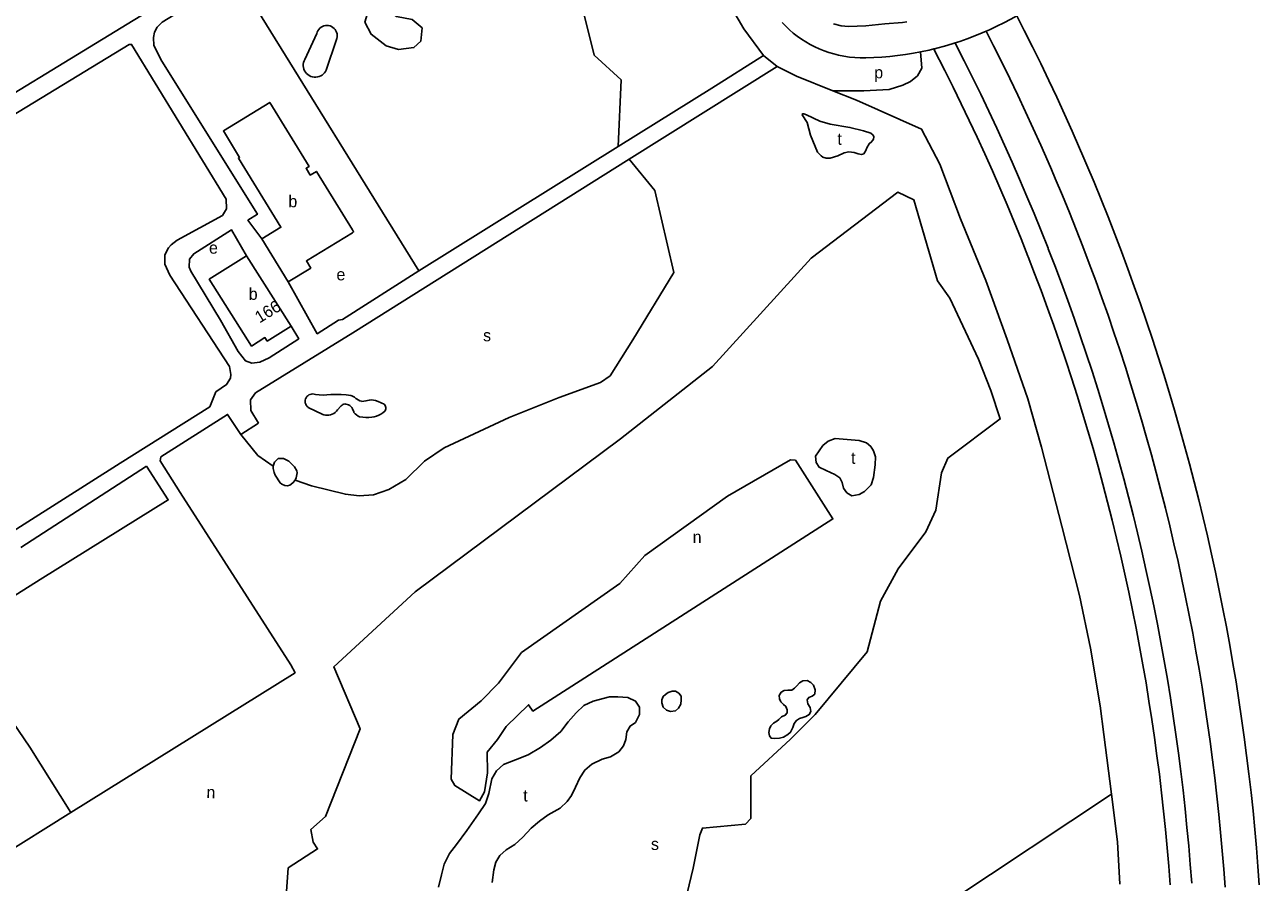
# Model space of a CAD drawing. Extents: x 156066 to 157805, y 383432 to 385631.
# Drawn here: x 157390.3 to 157803.6, y 384159.6 to 384446.9 of the extents above; entities that cross this region are included whole.
import ezdxf

# ---------------------------------------------------------------- set-up
doc = ezdxf.new("R2010")
doc.units = 0
for name, color, linetype in [('BLT_Basislijn', 7, 'Continuous'), ('BLT_Bebouwing', 7, 'Continuous'), ('BLT_Centroide', 7, 'Continuous'), ('BLT_Huisnummer', 7, 'Continuous'), ('BLT_Vlakafsluiter', 7, 'Continuous')]:
    doc.layers.add(name, color=color, linetype=linetype)

msp = doc.modelspace()

# ---------------------------------------------------------------- linework, layer by layer
at = {"layer": 'BLT_Basislijn'}
for p, q in [((157522.22, 384364.48), (157461.24, 384463.14)), ((157484.02, 384435.3), (157488.07, 384443.93)), ((157494.66, 384441.97), (157491.2, 384431.64)), ((157637.62, 384436.63), (157642.15, 384432.95)), ((157592.68, 384401.87), (157642.15, 384432.95)), ((157522.22, 384364.48), (157588.98, 384406.1)), ((157500.12, 384343.73), (157592.68, 384401.87)), ((157467.49, 384323.6), (157500.12, 384343.73)), ((157465.84, 384321.27), (157467.49, 384323.6)), ((157494.96, 384317.92), (157496.14, 384319.1)), ((157503.01, 384320.77), (157503.11, 384320.75)), ((157485.22, 384318.7), (157490.12, 384316.34)), ((157462.66, 384309.61), (157468.56, 384313.45)), ((157388.98, 384271.84), (157431.02, 384299.07))]:
    msp.add_line(p, q, dxfattribs=at)
for points in [[(157577.97, 384534.34), (157586.11, 384522.12), (157595.63, 384507.58), (157604.85, 384491.61), (157613.92, 384476.32), (157625.31, 384455.34), (157631.08, 384445.59), (157637.62, 384436.63)], [(157563.05, 384525.09), (157562.14, 384517.39), (157562.53, 384511.91), (157563.85, 384508.09), (157567.99, 384492.58), (157572.95, 384468.76), (157580.92, 384436.73), (157589.99, 384428.45), (157588.98, 384406.1)], [(157511.3, 384500), (157466.93, 384473.08), (157321.03, 384383.89)], [(157461.24, 384463.14), (157436.28, 384447.8), (157434.62, 384446.05), (157433.67, 384444.46), (157433.38, 384442.61), (157433.51, 384439.9), (157436.22, 384434.71), (157468.2, 384383.41), (157464.98, 384381.42), (157469.68, 384375.15)], [(157690.21, 384437.84), (157687.81, 384437.39), (157685.18, 384436.96), (157682.53, 384436.59), (157679.88, 384436.29), (157677.22, 384436.06), (157674.53, 384435.89), (157671.84, 384435.79), (157670.01, 384435.8), (157668.18, 384435.89), (157666.36, 384436.07), (157664.56, 384436.34), (157662.77, 384436.71), (157661.11, 384437.12), (157659.48, 384437.62), (157657.88, 384438.18), (157656.3, 384438.83), (157654.75, 384439.54), (157653.24, 384440.32), (157651.77, 384441.18), (157650.33, 384442.1), (157648.94, 384443.09), (157647.6, 384444.14), (157646.31, 384445.25), (157645.07, 384446.42), (157643.89, 384447.64)], [(157685.58, 384447.87), (157684.2, 384447.69), (157678.27, 384447.2), (157671.88, 384446.56), (157666.07, 384446.28), (157663.66, 384446.56), (157661.04, 384447.2)], [(157722.4, 384449.93), (157720.43, 384448.82), (157718.07, 384447.57), (157715.68, 384446.38), (157713.26, 384445.25), (157712.13, 384444.75)], [(157803.61, 384158.76), (157803.16, 384164.97), (157802.66, 384171.17), (157802.1, 384177.37), (157801.5, 384183.57), (157800.84, 384189.76), (157800.13, 384195.95), (157799.37, 384202.13), (157798.56, 384208.3), (157797.69, 384214.47), (157796.78, 384220.63), (157795.81, 384226.78), (157794.8, 384232.92), (157793.73, 384239.06), (157792.61, 384245.18), (157791.44, 384251.3), (157790.21, 384257.4), (157788.94, 384263.5), (157787.62, 384269.58), (157786.25, 384275.66), (157784.82, 384281.72), (157783.35, 384287.77), (157781.82, 384293.8), (157780.25, 384299.83), (157778.62, 384305.84), (157776.94, 384311.84), (157775.22, 384317.82), (157773.44, 384323.79), (157771.62, 384329.74), (157769.74, 384335.68), (157767.82, 384341.6), (157765.85, 384347.51), (157763.82, 384353.39), (157761.75, 384359.27), (157759.63, 384365.12), (157757.46, 384370.96), (157755.25, 384376.78), (157752.98, 384382.58), (157750.67, 384388.36), (157748.3, 384394.12), (157745.89, 384399.86), (157744.56, 384402.97), (157743.44, 384405.58), (157740.93, 384411.28), (157738.38, 384416.96), (157735.78, 384422.62), (157733.13, 384428.25), (157730.44, 384433.87), (157727.69, 384439.46), (157724.91, 384445.03), (157722.4, 384449.93)], [(157488.07, 384443.93), (157488.22, 384444.43), (157488.44, 384444.91), (157488.73, 384445.34), (157489.09, 384445.73), (157489.5, 384446.06), (157489.95, 384446.32), (157490.44, 384446.51), (157490.95, 384446.62), (157491.48, 384446.66), (157492, 384446.61), (157492.51, 384446.49), (157493, 384446.29), (157493.45, 384446.02), (157493.85, 384445.68), (157494.2, 384445.29), (157494.48, 384444.85), (157494.69, 384444.37), (157494.83, 384443.86), (157494.89, 384443.34), (157494.87, 384442.82), (157494.77, 384442.3), (157494.66, 384441.97)], [(157712.13, 384444.75), (157710.81, 384444.18), (157708.34, 384443.17), (157705.84, 384442.22), (157703.32, 384441.34), (157701.73, 384440.82)], [(157712.13, 384444.75), (157714.65, 384439.83), (157717.39, 384434.35), (157720.09, 384428.85), (157722.74, 384423.32), (157725.35, 384417.77), (157727.91, 384412.2), (157730.42, 384406.61), (157732.89, 384401), (157734, 384398.42), (157735.31, 384395.36), (157737.68, 384389.71), (157740.01, 384384.04), (157742.29, 384378.35), (157744.52, 384372.64), (157746.7, 384366.91), (157748.84, 384361.16), (157750.92, 384355.4), (157752.96, 384349.61), (157754.95, 384343.82), (157756.9, 384338), (157758.79, 384332.17), (157760.64, 384326.32), (157762.43, 384320.46), (157764.18, 384314.59), (157765.88, 384308.69), (157767.53, 384302.79), (157769.13, 384296.87), (157770.68, 384290.94), (157772.19, 384285), (157773.64, 384279.04), (157775.04, 384273.07), (157776.39, 384267.09), (157777.7, 384261.1), (157778.95, 384255.1), (157780.15, 384249.09), (157781.3, 384243.07), (157782.41, 384237.04), (157783.46, 384231), (157784.46, 384224.95), (157785.41, 384218.89), (157786.31, 384212.83), (157787.16, 384206.76), (157787.96, 384200.68), (157788.71, 384194.59), (157789.41, 384188.5), (157790.06, 384182.4), (157790.65, 384176.3), (157791.2, 384170.2), (157791.69, 384164.09), (157792.14, 384157.97)], [(157321.16, 384235.84), (157422.22, 384300), (157452.28, 384318.94), (157454.21, 384323.92), (157457.87, 384326.37), (157459.12, 384328.47), (157459.31, 384329.8), (157458.83, 384332.42), (157438.86, 384363.06), (157437.2, 384366.69), (157437.22, 384369.84), (157438.41, 384372.18), (157439.25, 384373.17), (157441.31, 384374.78), (157456.44, 384383.06), (157457.87, 384385.19), (157457.71, 384388.47), (157426.03, 384440.3), (157425.29, 384440.34), (157257.34, 384338.04)], [(157701.73, 384440.82), (157700.78, 384440.52), (157698.22, 384439.76), (157695.64, 384439.07), (157694.61, 384438.82)], [(157701.73, 384440.82), (157701.75, 384440.78)], [(157701.75, 384440.78), (157704.8, 384434.81), (157707.6, 384429.22), (157710.35, 384423.6), (157713.05, 384417.96), (157715.71, 384412.3), (157718.31, 384406.61), (157720.86, 384400.91), (157723.37, 384395.18), (157725.83, 384389.42), (157728.23, 384383.65), (157730.59, 384377.86), (157732.89, 384372.05), (157732.97, 384371.85), (157735.15, 384366.21), (157737.35, 384360.36), (157739.51, 384354.49), (157741.61, 384348.6), (157743.67, 384342.69), (157745.67, 384336.77), (157747.62, 384330.83), (157749.52, 384324.87), (157751.37, 384318.89), (157753.16, 384312.9), (157754.91, 384306.9), (157756.6, 384300.88), (157758.24, 384294.84), (157759.83, 384288.79), (157761.37, 384282.73), (157762.85, 384276.66), (157764.28, 384270.57), (157765.66, 384264.47), (157766.99, 384258.36), (157768.26, 384252.24), (157769.48, 384246.1), (157770.65, 384239.96), (157771.77, 384233.8), (157772.83, 384227.64), (157773.83, 384221.47), (157774.79, 384215.29), (157775.69, 384209.1), (157776.54, 384202.9), (157777.33, 384196.7), (157778.07, 384190.49), (157778.76, 384184.27), (157779.4, 384178.05), (157779.98, 384171.83), (157780.5, 384165.59), (157780.97, 384159.36)], [(157484.02, 384435.3), (157483.78, 384434.79), (157483.62, 384434.24), (157483.54, 384433.68), (157483.54, 384433.11), (157483.61, 384432.55), (157483.77, 384432), (157484, 384431.48), (157484.3, 384431), (157484.66, 384430.57), (157485.08, 384430.19), (157485.55, 384429.87), (157486.07, 384429.62), (157486.61, 384429.45), (157487.17, 384429.36), (157487.73, 384429.34), (157488.3, 384429.41), (157488.85, 384429.55), (157489.37, 384429.77), (157489.86, 384430.06), (157490.3, 384430.41), (157490.69, 384430.83), (157491.02, 384431.29), (157491.2, 384431.64)], [(157588.98, 384406.1), (157620.35, 384425.66), (157637.62, 384436.63)], [(157690.21, 384437.84), (157690.65, 384432.4), (157689.16, 384429.83), (157686.85, 384427.9), (157684.23, 384426.67), (157679.68, 384425.23), (157671.23, 384424.74), (157660.82, 384424.81)], [(157694.61, 384438.82), (157693.05, 384438.44), (157690.21, 384437.84)], [(157694.61, 384438.82), (157694.63, 384438.78)], [(157694.63, 384438.78), (157698.33, 384431.54), (157701.1, 384426), (157703.83, 384420.44), (157706.5, 384414.86), (157709.13, 384409.25), (157711.7, 384403.62), (157714.23, 384397.97), (157716.71, 384392.3), (157719.15, 384386.61), (157721.53, 384380.89), (157723.86, 384375.16), (157726.14, 384369.4), (157726.22, 384369.21), (157728.38, 384363.63), (157730.56, 384357.83), (157732.69, 384352.02), (157734.78, 384346.19), (157736.81, 384340.34), (157738.79, 384334.48), (157740.72, 384328.6), (157742.6, 384322.7), (157744.43, 384316.78), (157746.21, 384310.85), (157747.94, 384304.91), (157749.61, 384298.95), (157751.24, 384292.97), (157752.81, 384286.98), (157754.33, 384280.98), (157755.8, 384274.97), (157757.22, 384268.94), (157758.58, 384262.9), (157759.9, 384256.85), (157761.16, 384250.79), (157762.37, 384244.72), (157763.52, 384238.63), (157764.63, 384232.54), (157765.68, 384226.44), (157766.67, 384220.33), (157767.62, 384214.21), (157768.51, 384208.09), (157769.35, 384201.95), (157770.14, 384195.81), (157770.87, 384189.66), (157771.55, 384183.51), (157772.18, 384177.35), (157772.75, 384171.18), (157773.27, 384165.02), (157773.74, 384158.84)], [(157642.15, 384432.95), (157648.62, 384429.7), (157660.82, 384424.81)], [(157660.82, 384424.81), (157668.78, 384421.61), (157690.52, 384411.94), (157696.66, 384400.17), (157703.56, 384381.88), (157712.1, 384361.2), (157719.15, 384341.49), (157726.12, 384321.63), (157730.69, 384305.44), (157737.51, 384278.98), (157743.43, 384255.67), (157747.1, 384238.06), (157750.33, 384218.79), (157751.57, 384209.13)], [(157480.78, 384294.34), (157486.24, 384292.43), (157497.65, 384289.61), (157502.2, 384289.1), (157507.06, 384289.47), (157512.13, 384291.22), (157517.82, 384294.54), (157524.17, 384300.75), (157530.71, 384305.15), (157552.45, 384315.33), (157569.18, 384322.09), (157583.06, 384327.05), (157586.27, 384329.35), (157593.9, 384341.35), (157607.59, 384363.86), (157601.18, 384391.37), (157592.68, 384401.87)], [(157477.7, 384153.46), (157478.43, 384164.44), (157488.31, 384170.82), (157486.9, 384173.09), (157486.12, 384177.28), (157490.97, 384181.73), (157502.56, 384211.02), (157493.71, 384231.83), (157521.01, 384256.9), (157589.79, 384308.16), (157620.57, 384332.39), (157653.52, 384368.69), (157682.63, 384390.78), (157687.95, 384388.27), (157695.87, 384361.09), (157700, 384355.32), (157709.58, 384334.85), (157713.77, 384324.42), (157716.89, 384314.86), (157699.29, 384301.76), (157697.26, 384296.78), (157695.36, 384284.33), (157691.95, 384277.05), (157682.71, 384264.6), (157676.77, 384253.86), (157672.33, 384236.85), (157654.86, 384215.86), (157646.62, 384207.6), (157633.37, 384195.29), (157633.35, 384181.06), (157631.6, 384179.13), (157617.18, 384177.79), (157616.3, 384175.54), (157614.03, 384164.34), (157610.59, 384150.01)], [(157479.43, 384345.96), (157482, 384341.72), (157472.11, 384335.35), (157469, 384333.85), (157466.31, 384333.53), (157464.18, 384334.27), (157461.71, 384337.5), (157455.8, 384347.98), (157445.84, 384364.41), (157445.33, 384365.73), (157445.45, 384368.41), (157446.89, 384370.22), (157459.52, 384378.16), (157464.5, 384369.51)], [(157522.22, 384364.48), (157496.66, 384348.18), (157495.29, 384347.99), (157488.19, 384343.41), (157478.51, 384360.75)], [(157487.59, 384323.04), (157487.16, 384323.17), (157486.72, 384323.22), (157486.27, 384323.2), (157485.84, 384323.09), (157485.43, 384322.91), (157485.07, 384322.65), (157484.75, 384322.34), (157484.49, 384321.97), (157484.31, 384321.57), (157484.2, 384321.14), (157484.17, 384320.69), (157484.21, 384320.25), (157484.34, 384319.82), (157484.54, 384319.42), (157484.81, 384319.07), (157485.14, 384318.77), (157485.22, 384318.7)], [(157468.56, 384313.45), (157465.99, 384317.68), (157465.84, 384321.27)], [(157487.59, 384323.04), (157488.87, 384322.92), (157490.17, 384322.87), (157491.46, 384322.9), (157492.75, 384323.01), (157492.99, 384323.04)], [(157492.99, 384323.04), (157494.62, 384323.07), (157496.24, 384323.03), (157497.87, 384322.9), (157499.48, 384322.69), (157499.75, 384322.65)], [(157497.83, 384319.83), (157497.48, 384319.87), (157497.13, 384319.82), (157496.8, 384319.7), (157496.5, 384319.51), (157496.25, 384319.26), (157496.14, 384319.1)], [(157500.03, 384318.25), (157499.79, 384318.66), (157499.48, 384319.03), (157499.12, 384319.33), (157498.71, 384319.57), (157498.26, 384319.74), (157497.83, 384319.83)], [(157499.75, 384322.65), (157500.26, 384322.41), (157500.72, 384322.11), (157501.14, 384321.74), (157501.33, 384321.54)], [(157501.33, 384321.54), (157501.86, 384321.21), (157502.42, 384320.96), (157503.01, 384320.77)], [(157503.11, 384320.75), (157503.8, 384320.79), (157504.48, 384320.9), (157505.04, 384321.07)], [(157507.67, 384321.07), (157507.02, 384321.18), (157506.36, 384321.23), (157505.7, 384321.19), (157505.04, 384321.07)], [(157510.64, 384319.79), (157509.65, 384320.3), (157508.63, 384320.73), (157507.67, 384321.07)], [(157510.93, 384317.54), (157511.09, 384317.89), (157511.17, 384318.27), (157511.17, 384318.65), (157511.09, 384319.03), (157510.94, 384319.38), (157510.72, 384319.7), (157510.64, 384319.79)], [(157435.81, 384302.14), (157458.18, 384316.38), (157462.66, 384309.61)], [(157494.96, 384317.92), (157494.61, 384317.46), (157494.19, 384317.06), (157493.73, 384316.72), (157493.22, 384316.45), (157492.68, 384316.26), (157492.12, 384316.13), (157491.54, 384316.09), (157490.97, 384316.13), (157490.41, 384316.25), (157490.12, 384316.34)], [(157500.03, 384318.25), (157500.44, 384317.22), (157500.5, 384317.07)], [(157500.5, 384317.07), (157500.9, 384316.59), (157501.35, 384316.18), (157501.86, 384315.83), (157502.41, 384315.54)], [(157502.41, 384315.54), (157503.43, 384315.4), (157504.46, 384315.33), (157505.49, 384315.35), (157506.52, 384315.45), (157507.31, 384315.58)], [(157507.31, 384315.58), (157508.08, 384315.81), (157508.83, 384316.11), (157509.54, 384316.49), (157510.2, 384316.93), (157510.83, 384317.44), (157510.93, 384317.54)], [(157462.66, 384309.61), (157468.33, 384302.64), (157473.47, 384299.03)], [(157431.02, 384299.07), (157438.34, 384287.74), (157395.47, 384261.06)], [(157435.81, 384302.14), (157435.58, 384300.77), (157442.36, 384290.25), (157479.39, 384232.46), (157480.77, 384229.86), (157405.66, 384183.03)], [(157473.47, 384299.03), (157473.92, 384300.4), (157475.12, 384301.59), (157476.86, 384301.66), (157478.66, 384300.73), (157480.65, 384298.87), (157481.39, 384297.46), (157481.45, 384296.86), (157481.14, 384295.14), (157480.78, 384294.34)], [(157480.78, 384294.34), (157480.04, 384293.41), (157479.08, 384292.7), (157478.26, 384292.43), (157477.32, 384292.52), (157476.32, 384292.98), (157475.83, 384293.45), (157474.17, 384296.05), (157473.83, 384296.9), (157473.49, 384298.28), (157473.47, 384299.03)], [(157372.75, 384226.84), (157364.27, 384240.49), (157364.05, 384241.3), (157395.47, 384261.06)], [(157528.85, 384158.03), (157529.82, 384162.15), (157530.65, 384165.67), (157532.52, 384169.27), (157534.85, 384172.34), (157538.29, 384176.99), (157542.19, 384182.54), (157544.51, 384185.98), (157545.71, 384189.36), (157546.69, 384194.3), (157548.26, 384197), (157550.58, 384199.1), (157554.63, 384200.67), (157558.83, 384202.32), (157562.95, 384204.8), (157566.47, 384207.27), (157569.77, 384210.19), (157572.25, 384213.34), (157574.87, 384216.41), (157577.49, 384218.89), (157580.64, 384220.31), (157586.04, 384221.81), (157588.81, 384221.81), (157592.18, 384221.51), (157594.81, 384220.31), (157596.08, 384218.29), (157596.15, 384215.81), (157594.73, 384213.12), (157593.01, 384211.99), (157591.88, 384210.04), (157591.58, 384207.49), (157590.76, 384205.4), (157589.18, 384203.37), (157586.34, 384201.72), (157583.56, 384200.9), (157580.12, 384199.25), (157577.79, 384197.23), (157576.14, 384194.6), (157574.64, 384191.53), (157573.37, 384188.68), (157571.87, 384186.66), (157569.55, 384184.49), (157565.5, 384182.24), (157562.58, 384180.14), (157559.8, 384177.81), (157557.03, 384174.74), (157554.41, 384172.34), (157551.41, 384170.47), (157549.39, 384168.67), (157547.96, 384166.42), (157547.36, 384163.8), (157546.76, 384159.53)], [(157382.55, 384218.81), (157391.95, 384204.86), (157405.66, 384183.03)], [(157751.57, 384209.13), (157754.15, 384189.17)], [(157754.15, 384189.17), (157700, 384153.26), (157578.07, 384073.38), (157500.22, 384022.86)], [(157754.15, 384189.17), (157756.16, 384173.17), (157756.97, 384158.98)], [(157369.67, 384160.28), (157381.34, 384167.89), (157405.66, 384183.03)]]:
    msp.add_lwpolyline(points, dxfattribs=at)
for points in [[(157514.8, 384449.69), (157512.15, 384451.46), (157509.05, 384452.27), (157506.55, 384451.69), (157504.89, 384450.38), (157504.16, 384447.78), (157506.31, 384443.71), (157511.27, 384439.83), (157515.36, 384438.64), (157520.56, 384439.23), (157522.84, 384441.4), (157523.35, 384445.86), (157519.96, 384448.66)], [(157650.6, 384416.71), (157650.65, 384417.05), (157651.13, 384417.08), (157651.99, 384416.75), (157656.46, 384414.62), (157659.89, 384413.58), (157666.57, 384412.5), (157671.12, 384411.42), (157673.52, 384410.57), (157674.3, 384409.94), (157674.59, 384409.31), (157674.43, 384408.63), (157673.87, 384407.79), (157672.98, 384407.07), (157672.26, 384405.73), (157671.89, 384404.78), (157671.16, 384403.66), (157670.43, 384403.44), (157669.27, 384403.61), (157668, 384404.15), (157666.23, 384404.29), (157664.67, 384403.97), (157662.55, 384403.01), (157659.95, 384402.18), (157658.61, 384402.17), (157657.5, 384402.58), (157656.88, 384403.01), (157655.64, 384404.19), (157653.34, 384409.95), (157652.18, 384414.17)], [(157661.59, 384308.27), (157669.64, 384307.59), (157672.08, 384306.88), (157673.5, 384305.6), (157674.4, 384304.14), (157675.11, 384302.19), (157675, 384299.53), (157674.44, 384295.22), (157673.62, 384292.79), (157671.48, 384290.58), (157669.64, 384289.57), (157667.24, 384289.15), (157665.48, 384290.13), (157664.4, 384291.7), (157663.91, 384293.61), (157663.16, 384295.15), (157661.55, 384296.27), (157658.59, 384297.62), (157656.3, 384298.67), (157655.29, 384300.32), (157655.07, 384302.42), (157657.5, 384305.98), (157659.22, 384307.4)], [(157646.66, 384301.18), (157648.31, 384301.01), (157660.84, 384281.37), (157560.4, 384216.97), (157558.97, 384219.14), (157551.47, 384211.87), (157548.59, 384207.44), (157545.11, 384203.28), (157545.26, 384196.36), (157544.2, 384189.96), (157542.58, 384186.95), (157534.29, 384192.02), (157533.08, 384194.19), (157533.62, 384209.13), (157535.58, 384214.33), (157543.07, 384220.43), (157548.86, 384226.35), (157556.63, 384236.61), (157589.47, 384259.7), (157597.84, 384269.09), (157625.61, 384288.94)], [(157649.67, 384226.42), (157650.79, 384227.13), (157652.29, 384227.21), (157653.49, 384226.61), (157654.35, 384225.71), (157654.95, 384224.06), (157654.77, 384222.71), (157653.94, 384221.96), (157652.78, 384221.59), (157652.18, 384220.76), (157652.44, 384219.41), (157653.27, 384218.14), (157653.45, 384216.83), (157652.93, 384215.81), (157651.84, 384215.18), (157650.79, 384214.84), (157649.63, 384214.47), (157648.66, 384213.87), (157647.83, 384212.82), (157647.42, 384211.54), (157646.71, 384209.93), (157645.77, 384209.14), (157644.31, 384208.24), (157642.92, 384207.87), (157641.46, 384207.76), (157640.19, 384207.87), (157639.66, 384208.69), (157639.44, 384209.82), (157639.59, 384211.09), (157640.04, 384212.1), (157640.94, 384213), (157642.1, 384213.6), (157642.7, 384214.2), (157643.67, 384215.06), (157644.87, 384215.66), (157645.55, 384216.41), (157645.55, 384217.43), (157645.1, 384218.55), (157644.35, 384219.22), (157643.41, 384220.05), (157642.92, 384221.14), (157642.81, 384222.26), (157643.49, 384223.31), (157644.53, 384223.91), (157645.77, 384223.95), (157647.12, 384223.98), (157647.98, 384224.66), (157648.81, 384225.48)], [(157605.67, 384223.2), (157607.02, 384223.61), (157608.15, 384223.61), (157609.31, 384222.97), (157610.02, 384222.04), (157610.1, 384220.76), (157609.91, 384219.26), (157609.12, 384217.95), (157608.15, 384217.13), (157606.5, 384216.86), (157605.19, 384217.35), (157604.02, 384218.36), (157603.61, 384219.75), (157603.57, 384220.8), (157603.99, 384221.89), (157604.77, 384222.6)]]:
    msp.add_lwpolyline(points, close=True, dxfattribs=at)
at = {"layer": 'BLT_Bebouwing'}
for p, q in [((157478.51, 384360.75), (157469.68, 384375.15)), ((157464.5, 384369.51), (157479.43, 384345.96))]:
    msp.add_line(p, q, dxfattribs=at)
for points in [[(157469.68, 384375.15), (157476.04, 384379.05), (157461.81, 384402.25), (157462.2, 384402.49), (157456.78, 384411.34), (157472.33, 384420.87), (157485.46, 384399.44), (157484.47, 384398.83), (157485.88, 384396.54), (157487.94, 384397.8), (157500, 384378.16), (157500.4, 384377.5), (157500, 384377.25), (157484.58, 384367.8), (157486.06, 384365.38), (157478.51, 384360.75)], [(157464.5, 384369.51), (157452.08, 384361.64), (157466.25, 384339.29), (157470.72, 384342.13), (157471.48, 384340.93), (157479.43, 384345.96)]]:
    msp.add_lwpolyline(points, dxfattribs=at)
at = {"layer": 'BLT_Vlakafsluiter'}
msp.add_lwpolyline([(157701.75, 384440.78), (157700.8, 384440.47), (157698.24, 384439.72), (157695.66, 384439.02), (157694.63, 384438.78)], dxfattribs=at)

# ---------------------------------------------------------------- texts
at = {"layer": 'BLT_Centroide'}
for s, p in [('p', (157674.7, 384428.95)), ('t', (157662.33, 384406.7)), ('b', (157478.55, 384385.77)), ('e', (157451.97, 384370.22)), ('e', (157494.65, 384361.28)), ('b', (157465.28, 384354.75)), ('s', (157543.73, 384340.86)), ('t', (157666.91, 384299.83)), ('n', (157613.91, 384273.32)), ('t', (157557.18, 384186.73)), ('s', (157599.94, 384170.47))]:
    msp.add_text(s, height=4, dxfattribs=at).set_placement(p)
msp.add_text('n', height=4, rotation=359, dxfattribs=at).set_placement((157451.08, 384187.85))
at = {"layer": 'BLT_Huisnummer'}
msp.add_text('166', height=4, rotation=31.5063, dxfattribs=at).set_placement((157468.88, 384346.81))

doc.saveas('drawing.dxf')
